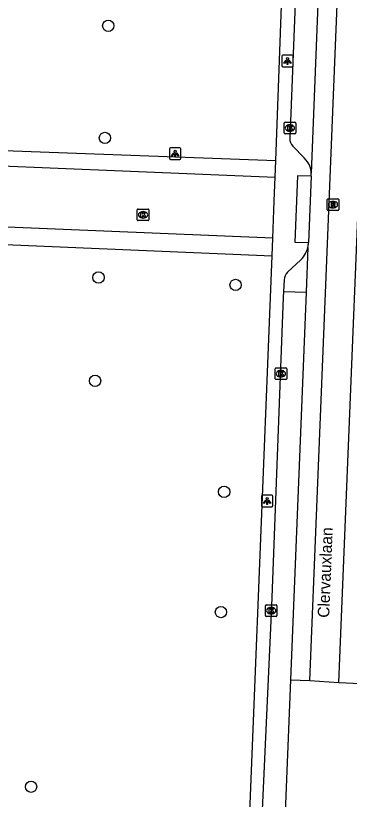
# Model space of a CAD drawing. Extents: x 160787 to 161428, y 386828 to 387483.
# Drawn here: x 160965.3 to 160994.1, y 387090.3 to 387157.9 of the extents above; entities that cross this region are included whole.
import ezdxf

# ---------------------------------------------------------------- set-up
doc = ezdxf.new("R2010")
doc.units = 0
for name, color, linetype in [('IMGEO_Boom', 7, 'Continuous'), ('IMGEO_Kolk', 7, 'Continuous'), ('IMGEO_Lichtpunt', 7, 'Continuous'), ('IMGEO_Openbare_ruimte_label', 7, 'Continuous'), ('IMGEO_Parkeervlak_gesloten', 7, 'Continuous'), ('IMGEO_Parkeervlak_open', 7, 'Continuous'), ('IMGEO_Rijbaan_lokaal_gesloten', 7, 'Continuous'), ('IMGEO_Rijbaan_lokaal_open', 7, 'Continuous'), ('IMGEO_Rioolput', 7, 'Continuous'), ('IMGEO_Voetpad_open', 7, 'Continuous')]:
    doc.layers.add(name, color=color, linetype=linetype)

msp = doc.modelspace()

# ---------------------------------------------------------------- linework, layer by layer
at = {"layer": 'IMGEO_Boom'}
for centre in [(160973.335, 387157.044), (160973.049, 387147.366), (160972.497, 387135.313), (160984.328, 387134.674), (160972.197, 387126.397), (160983.335, 387116.817), (160983.062, 387106.441), (160966.675, 387091.364)]:
    msp.add_circle(centre, 0.489, dxfattribs=at)
at = {"layer": 'IMGEO_Kolk'}
for p, q in [((160988.515, 387147.792), (160988.515, 387148.644)), ((160988.59, 387148.718), (160989.442, 387148.718)), ((160989.003, 387148.498), (160989.028, 387148.498)), ((160989.516, 387148.644), (160989.516, 387147.792)), ((160989.442, 387147.718), (160988.59, 387147.718)), ((160989.026, 387147.938), (160989.001, 387147.938)), ((160975.841, 387140.3), (160975.841, 387141.152)), ((160975.916, 387141.226), (160976.768, 387141.226)), ((160976.329, 387141.006), (160976.354, 387141.006)), ((160976.842, 387141.152), (160976.842, 387140.3)), ((160976.768, 387140.226), (160975.916, 387140.226)), ((160976.352, 387140.446), (160976.327, 387140.446)), ((160987.737, 387126.582), (160987.737, 387127.434)), ((160987.812, 387127.508), (160988.664, 387127.508)), ((160988.225, 387127.288), (160988.25, 387127.288)), ((160988.738, 387127.434), (160988.738, 387126.582)), ((160988.664, 387126.508), (160987.812, 387126.508)), ((160988.248, 387126.728), (160988.223, 387126.728)), ((160986.896, 387106.136), (160986.896, 387106.988)), ((160986.971, 387107.062), (160987.823, 387107.062)), ((160987.384, 387106.842), (160987.409, 387106.842)), ((160987.897, 387106.988), (160987.897, 387106.136)), ((160987.407, 387106.282), (160987.382, 387106.282)), ((160987.823, 387106.062), (160986.971, 387106.062))]:
    msp.add_line(p, q, dxfattribs=at)
for points in [[(160988.515, 387147.792), (160988.515, 387148.644)], [(160988.59, 387148.718), (160989.442, 387148.718)], [(160988.836, 387148.418), (160988.959, 387148.418), (160988.959, 387148.267), (160989.089, 387148.418), (160989.253, 387148.418), (160989.107, 387148.267), (160989.26, 387148.018), (160989.108, 387148.018), (160989.023, 387148.182), (160988.959, 387148.115), (160988.959, 387148.018), (160988.836, 387148.018), (160988.836, 387148.418)], [(160989.516, 387148.644), (160989.516, 387147.792)], [(160989.442, 387147.718), (160988.59, 387147.718)], [(160975.841, 387140.3), (160975.841, 387141.152)], [(160975.916, 387141.226), (160976.768, 387141.226)], [(160976.162, 387140.926), (160976.285, 387140.926), (160976.285, 387140.775), (160976.415, 387140.926), (160976.579, 387140.926), (160976.433, 387140.775), (160976.586, 387140.526), (160976.434, 387140.526), (160976.349, 387140.69), (160976.285, 387140.623), (160976.285, 387140.526), (160976.162, 387140.526), (160976.162, 387140.926)], [(160976.842, 387141.152), (160976.842, 387140.3)], [(160976.768, 387140.226), (160975.916, 387140.226)], [(160987.737, 387126.582), (160987.737, 387127.434)], [(160987.812, 387127.508), (160988.664, 387127.508)], [(160988.058, 387127.208), (160988.181, 387127.208), (160988.181, 387127.057), (160988.311, 387127.208), (160988.475, 387127.208), (160988.329, 387127.057), (160988.482, 387126.808), (160988.33, 387126.808), (160988.245, 387126.972), (160988.181, 387126.905), (160988.181, 387126.808), (160988.058, 387126.808), (160988.058, 387127.208)], [(160988.738, 387127.434), (160988.738, 387126.582)], [(160988.664, 387126.508), (160987.812, 387126.508)], [(160986.896, 387106.136), (160986.896, 387106.988)], [(160986.971, 387107.062), (160987.823, 387107.062)], [(160987.897, 387106.988), (160987.897, 387106.136)], [(160987.217, 387106.762), (160987.34, 387106.762), (160987.34, 387106.611), (160987.47, 387106.762), (160987.634, 387106.762), (160987.488, 387106.611), (160987.641, 387106.362), (160987.489, 387106.362), (160987.404, 387106.526), (160987.34, 387106.459), (160987.34, 387106.362), (160987.217, 387106.362), (160987.217, 387106.762)], [(160987.823, 387106.062), (160986.971, 387106.062)]]:
    msp.add_lwpolyline(points, dxfattribs=at)
for centre, start, end in [((160988.592, 387148.642), 91.55205, 178.44795), ((160988.592, 387148.642), 91.55205, 178.44795), ((160989.44, 387148.642), 1.55205, 88.44795), ((160989.44, 387148.642), 1.55205, 88.44795), ((160988.592, 387147.794), 181.55205, 268.44795), ((160988.592, 387147.794), 181.55205, 268.44795), ((160989.44, 387147.794), 271.55205, 358.44795), ((160989.44, 387147.794), 271.55205, 358.44795), ((160975.918, 387141.15), 91.55205, 178.44795), ((160975.918, 387141.15), 91.55205, 178.44795), ((160976.766, 387141.15), 1.55205, 88.44795), ((160976.766, 387141.15), 1.55205, 88.44795), ((160975.918, 387140.302), 181.55205, 268.44795), ((160975.918, 387140.302), 181.55205, 268.44795), ((160976.766, 387140.302), 271.55205, 358.44795), ((160976.766, 387140.302), 271.55205, 358.44795), ((160987.814, 387127.432), 91.55205, 178.44795), ((160987.814, 387127.432), 91.55205, 178.44795), ((160988.662, 387127.432), 1.55205, 88.44795), ((160988.662, 387127.432), 1.55205, 88.44795), ((160987.814, 387126.584), 181.55205, 268.44795), ((160987.814, 387126.584), 181.55205, 268.44795), ((160988.662, 387126.584), 271.55205, 358.44795), ((160988.662, 387126.584), 271.55205, 358.44795), ((160986.973, 387106.986), 91.55205, 178.44795), ((160986.973, 387106.986), 91.55205, 178.44795), ((160987.821, 387106.986), 1.55205, 88.44795), ((160987.821, 387106.986), 1.55205, 88.44795), ((160986.973, 387106.138), 181.55205, 268.44795), ((160986.973, 387106.138), 181.55205, 268.44795), ((160987.821, 387106.138), 271.55205, 358.44795), ((160987.821, 387106.138), 271.55205, 358.44795)]:
    msp.add_arc(centre, 0.0765, start, end, dxfattribs=at)
for centre, major_axis, ratio, start_param, end_param in [((160989.002, 387148.218), (-0.387, 0.002), 0.722429, 4.712389, 7.853982), ((160989.027, 387148.218), (-0.39, 0.002), 0.717154, 1.570796, 4.712389), ((160976.328, 387140.726), (-0.387, 0.002), 0.722429, 4.712389, 7.853982), ((160976.353, 387140.726), (-0.39, 0.002), 0.717154, 1.570796, 4.712389), ((160988.224, 387127.008), (-0.387, 0.002), 0.722429, 4.712389, 7.853982), ((160988.249, 387127.008), (-0.39, 0.002), 0.717154, 1.570796, 4.712389), ((160987.383, 387106.562), (-0.387, 0.002), 0.722429, 4.712389, 7.853982), ((160987.408, 387106.562), (-0.39, 0.002), 0.717154, 1.570796, 4.712389)]:
    msp.add_ellipse(centre, major_axis=major_axis, ratio=ratio, start_param=start_param, end_param=end_param, dxfattribs=at)
at = {"layer": 'IMGEO_Lichtpunt'}
for p, q in [((160988.307, 387154.411), (160988.307, 387153.604)), ((160988.307, 387154.411), (160988.307, 387153.604)), ((160989.209, 387154.506), (160988.401, 387154.506)), ((160989.209, 387154.506), (160988.401, 387154.506)), ((160989.303, 387153.604), (160989.303, 387154.411)), ((160989.303, 387153.604), (160989.303, 387154.411)), ((160988.401, 387153.51), (160989.209, 387153.51)), ((160988.401, 387153.51), (160989.209, 387153.51)), ((160978.613, 387146.415), (160978.613, 387145.608)), ((160978.613, 387146.415), (160978.613, 387145.608)), ((160979.515, 387146.51), (160978.707, 387146.51)), ((160979.515, 387146.51), (160978.707, 387146.51)), ((160979.609, 387145.608), (160979.609, 387146.415)), ((160979.609, 387145.608), (160979.609, 387146.415)), ((160978.707, 387145.514), (160979.515, 387145.514)), ((160978.707, 387145.514), (160979.515, 387145.514)), ((160986.551, 387116.435), (160986.551, 387115.628)), ((160986.551, 387116.435), (160986.551, 387115.628)), ((160987.453, 387116.53), (160986.645, 387116.53)), ((160987.453, 387116.53), (160986.645, 387116.53)), ((160987.547, 387115.628), (160987.547, 387116.435)), ((160987.547, 387115.628), (160987.547, 387116.435)), ((160986.645, 387115.534), (160987.453, 387115.534)), ((160986.645, 387115.534), (160987.453, 387115.534))]:
    msp.add_line(p, q, dxfattribs=at)
for points in [[(160988.681, 387154.075), (160988.72, 387154.047), (160988.532, 387153.785), (160988.494, 387153.812), (160988.681, 387154.075)], [(160988.783, 387154.027), (160988.83, 387154.027), (160988.83, 387153.705), (160988.783, 387153.705), (160988.783, 387154.027)], [(160988.893, 387154.047), (160988.931, 387154.074), (160989.118, 387153.812), (160989.079, 387153.784), (160988.893, 387154.047)], [(160978.987, 387146.079), (160979.026, 387146.051), (160978.838, 387145.789), (160978.8, 387145.816), (160978.987, 387146.079)], [(160979.199, 387146.051), (160979.237, 387146.078), (160979.424, 387145.816), (160979.385, 387145.788), (160979.199, 387146.051)], [(160979.089, 387146.031), (160979.136, 387146.031), (160979.136, 387145.709), (160979.089, 387145.709), (160979.089, 387146.031)], [(160986.925, 387116.099), (160986.964, 387116.071), (160986.776, 387115.809), (160986.738, 387115.836), (160986.925, 387116.099)], [(160987.027, 387116.051), (160987.074, 387116.051), (160987.074, 387115.729), (160987.027, 387115.729), (160987.027, 387116.051)], [(160987.137, 387116.071), (160987.175, 387116.098), (160987.362, 387115.836), (160987.323, 387115.808), (160987.137, 387116.071)]]:
    msp.add_lwpolyline(points, dxfattribs=at)
for centre in [(160988.806, 387154.209), (160979.112, 387146.213), (160987.05, 387116.233)]:
    msp.add_circle(centre, 0.0994, dxfattribs=at)
for centre, start, end in [((160988.401, 387154.411), 90, 180), ((160988.401, 387154.411), 90, 180), ((160989.209, 387154.411), 0, 90), ((160989.209, 387154.411), 0, 90), ((160988.401, 387153.604), 180, 270), ((160988.401, 387153.604), 180, 270), ((160989.209, 387153.604), 270, 0), ((160989.209, 387153.604), 270, 360), ((160978.707, 387146.415), 90, 180), ((160978.707, 387146.415), 90, 180), ((160979.515, 387146.415), 0, 90), ((160979.515, 387146.415), 0, 90), ((160978.707, 387145.608), 180, 270), ((160978.707, 387145.608), 180, 270), ((160979.515, 387145.608), 270, 0), ((160979.515, 387145.608), 270, 360), ((160986.645, 387116.435), 90, 180), ((160986.645, 387116.435), 90, 180), ((160987.453, 387116.435), 0, 90), ((160987.453, 387116.435), 0, 90), ((160986.645, 387115.628), 180, 270), ((160986.645, 387115.628), 180, 270), ((160987.453, 387115.628), 270, 0), ((160987.453, 387115.628), 270, 360)]:
    msp.add_arc(centre, 0.0946, start, end, dxfattribs=at)
at = {"layer": 'IMGEO_Parkeervlak_gesloten'}
msp.add_lwpolyline([(160988.459, 387134.105), (160990.419, 387134.055)], dxfattribs=at)
at = {"layer": 'IMGEO_Parkeervlak_open'}
for points in [[(160944.778, 387147.003), (160987.788, 387145.408)], [(160958.703, 387138.397), (160958.977, 387138.385), (160987.482, 387137.188)]]:
    msp.add_lwpolyline(points, dxfattribs=at)
at = {"layer": 'IMGEO_Rijbaan_lokaal_gesloten'}
for points in [[(160990.739, 387100.543), (160993.392, 387166.012), (160997.526, 387268.031)], [(160992.149, 387177.22), (160990.856, 387144.333)], [(160993.223, 387100.345), (160995.922, 387165.873), (160996.658, 387175.171)], [(160990.846, 387144.057), (160990.614, 387138.336)], [(160990.56, 387137.914), (160990.419, 387134.055)], [(160990.419, 387134.055), (160989.068, 387100.6)], [(160989.068, 387100.6), (160988.543, 387087.729)], [(160989.068, 387100.6), (160990.739, 387100.543)], [(160990.739, 387100.543), (160993.223, 387100.345)], [(160993.223, 387100.345), (160995.117, 387100.282)]]:
    msp.add_lwpolyline(points, dxfattribs=at)
for centre, radius, start, end in [((160988.947, 387144.264), 1.911, 353.78035, 2.0696), ((160988.358, 387138.41), 2.257, 347.30019, 358.11569)]:
    msp.add_arc(centre, radius, start, end, dxfattribs=at)
at = {"layer": 'IMGEO_Rijbaan_lokaal_open'}
for points in [[(160944.724, 387145.758), (160987.735, 387143.98)], [(160987.539, 387138.707), (160987.659, 387141.927), (160987.735, 387143.98)], [(160987.539, 387138.707), (160959.041, 387139.904), (160958.766, 387139.916), (160958.703, 387138.397)]]:
    msp.add_lwpolyline(points, dxfattribs=at)
at = {"layer": 'IMGEO_Rioolput'}
for p, q in [((160992.229, 387141.184), (160992.229, 387142.036)), ((160992.304, 387142.11), (160993.156, 387142.11)), ((160993.23, 387142.036), (160993.23, 387141.184)), ((160992.74, 387141.33), (160992.715, 387141.33)), ((160992.717, 387141.89), (160992.742, 387141.89)), ((160993.156, 387141.11), (160992.304, 387141.11))]:
    msp.add_line(p, q, dxfattribs=at)
for points in [[(160992.229, 387141.184), (160992.229, 387142.036)], [(160992.304, 387142.11), (160993.156, 387142.11)], [(160993.23, 387142.036), (160993.23, 387141.184)], [(160992.818, 387141.808), (160992.566, 387141.81), (160992.566, 387141.41)], [(160992.566, 387141.41), (160992.69, 387141.41), (160992.69, 387141.572), (160992.701, 387141.572)], [(160992.744, 387141.729), (160992.69, 387141.729), (160992.69, 387141.648)], [(160992.69, 387141.648), (160992.742, 387141.648)], [(160992.748, 387141.543), (160992.819, 387141.41), (160992.959, 387141.41), (160992.894, 387141.536)], [(160993.156, 387141.11), (160992.304, 387141.11)]]:
    msp.add_lwpolyline(points, dxfattribs=at)
for centre, radius, start, end in [((160992.306, 387142.034), 0.0765, 91.55205, 178.44795), ((160992.306, 387142.034), 0.0765, 91.55205, 178.44795), ((160993.154, 387142.034), 0.0765, 1.55205, 88.44795), ((160993.154, 387142.034), 0.0765, 1.55205, 88.44795), ((160992.7, 387141.519), 0.0533, 26.02933, 88.69889), ((160992.726, 387141.837), 0.19, 274.7715, 282.96867), ((160992.75, 387141.633), 0.0964, 77.00612, 93.18647), ((160992.764, 387141.69), 0.0378, 276.66336, 79.67722), ((160992.817, 387141.698), 0.109, 350.36119, 89.41601), ((160992.815, 387141.698), 0.112, 277.58423, 350.98172), ((160992.799, 387141.483), 0.108, 29.51342, 73.79051), ((160992.306, 387141.186), 0.0765, 181.55205, 268.44795), ((160992.306, 387141.186), 0.0765, 181.55205, 268.44795), ((160993.154, 387141.186), 0.0765, 271.55205, 358.44795), ((160993.154, 387141.186), 0.0765, 271.55205, 358.44795)]:
    msp.add_arc(centre, radius, start, end, dxfattribs=at)
for centre, major_axis, ratio, start_param, end_param in [((160992.716, 387141.61), (-0.387, 0.002), 0.722429, 4.712389, 7.853982), ((160992.741, 387141.61), (-0.39, 0.002), 0.717154, 1.570796, 4.712389)]:
    msp.add_ellipse(centre, major_axis=major_axis, ratio=ratio, start_param=start_param, end_param=end_param, dxfattribs=at)
at = {"layer": 'IMGEO_Voetpad_open'}
for points in [[(160987.788, 387145.408), (160990.127, 387209.121)], [(160990.078, 387174.351), (160989.002, 387147.322)], [(160989.262, 387146.648), (160990.232, 387145.639)], [(160987.735, 387143.98), (160987.788, 387145.408)], [(160990.846, 387144.057), (160989.657, 387144.078), (160989.433, 387138.362), (160990.614, 387138.336)], [(160987.482, 387137.188), (160987.539, 387138.707)], [(160984.917, 387073.364), (160987.482, 387137.188)], [(160989.96, 387136.848), (160988.809, 387135.782)], [(160988.504, 387135.106), (160988.459, 387134.105)], [(160988.459, 387134.105), (160988.437, 387133.61), (160987.413, 387106.954), (160986.204, 387080.553), (160985.955, 387075.106), (160985.95, 387074.857)]]:
    msp.add_lwpolyline(points, dxfattribs=at)
for centre, radius, start, end in [((160989.919, 387147.289), 0.917, 177.90997, 224.27893), ((160989.024, 387144.26), 1.833, 21.19024, 48.77232), ((160989.027, 387144.259), 1.831, 2.30305, 21.24904), ((160988.439, 387138.408), 2.179, 314.26889, 331.78404), ((160988.452, 387138.399), 2.163, 331.83915, 347.04876), ((160989.54, 387135.045), 1.038, 134.78774, 176.64405)]:
    msp.add_arc(centre, radius, start, end, dxfattribs=at)

# ---------------------------------------------------------------- texts
at = {"layer": 'IMGEO_Openbare_ruimte_label'}
msp.add_text('Clervauxlaan', height=1, rotation=87.7071, dxfattribs=at).set_placement((160992.4, 387105.932))

doc.saveas('drawing.dxf')
